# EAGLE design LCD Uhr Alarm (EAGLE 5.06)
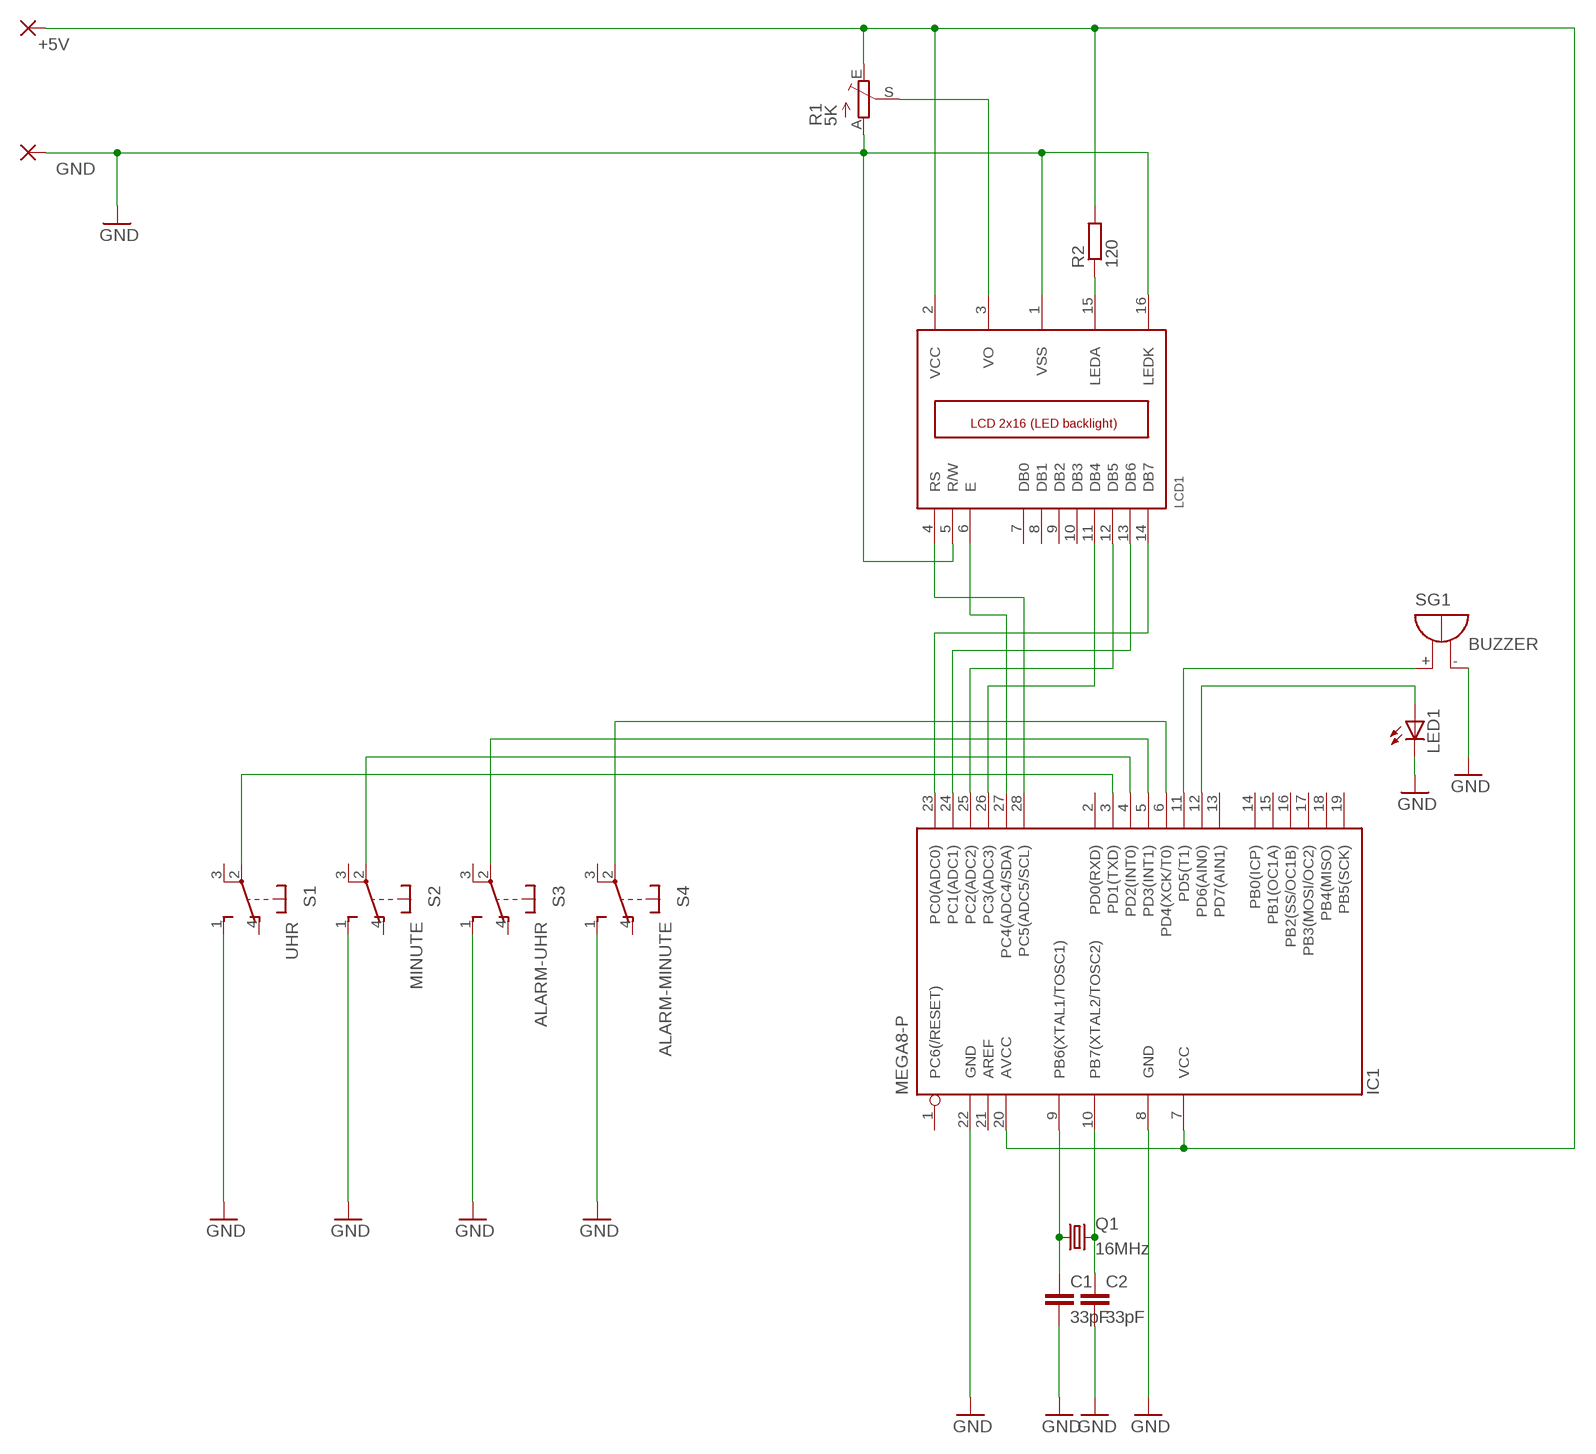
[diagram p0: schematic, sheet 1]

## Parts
+5V  WIREPAD2,54/1,0  [2,54/1,0]
C1  33pF  C2,5-3  [C2.5-3]
C2  33pF  C2,5-3  [C2.5-3]
GND  WIREPAD2,54/1,0  [2,54/1,0]
IC1  MEGA8-P  [DIL28-3]
LCD1  LCD_2X16  [HY-1602F]
LED1  LED5MM  [LED5MM]
Q1  16MHz  CRYSTALHC18U-V  [HC18U-V]
R1  5K  TRIM_EU-CA6V  [CA6V]
R2  120  R-EU_0207/10  [0207/10]
S1  UHR  SRK  [SRK]
S2  MINUTE  SRK  [SRK]
S3  ALARM-UHR  SRK  [SRK]
S4  ALARM-MINUTE  SRK  [SRK]
SG1  BUZZER  EB2505  [EB2505]

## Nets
GND: C1.2 C2.2 GND.1(P) IC1.8(GND) IC1.22(GND) LCD1.1(VSS) LCD1.5(R/W) LCD1.16(LEDK) LED1.K(C) R1.A S1.1(S) S2.1(S) S3.1(S) S4.1(S) SG1.-
N$1: IC1.11(PD5(T1)) SG1.+
N$2: +5V.1(P) IC1.7(VCC) IC1.20(AVCC) LCD1.2(VCC) R1.E R2.2
N$3: LCD1.3(VO) R1.S
N$4: IC1.3(PD1(TXD)) S1.2(P)
N$5: IC1.26(PC3(ADC3)) LCD1.11(DB4)
N$6: IC1.25(PC2(ADC2)) LCD1.12(DB5)
N$7: IC1.24(PC1(ADC1)) LCD1.13(DB6)
N$8: IC1.12(PD6(AIN0)) LED1.A
N$9: IC1.23(PC0(ADC0)) LCD1.14(DB7)
N$10: LCD1.15(LEDA) R2.1
N$11: IC1.28(PC5(ADC5/SCL)) LCD1.4(RS)
N$12: IC1.4(PD2(INT0)) S2.2(P)
N$13: C2.1 IC1.10(PB7(XTAL2/TOSC2)) Q1.2
N$14: C1.1 IC1.9(PB6(XTAL1/TOSC1)) Q1.1
N$15: IC1.5(PD3(INT1)) S3.2(P)
N$16: IC1.27(PC4(ADC4/SDA)) LCD1.6(E)
N$17: IC1.6(PD4(XCK/T0)) S4.2(P)
Unconnected: IC1.1(PC6(/RESET)) IC1.2(PD0(RXD)) IC1.13(PD7(AIN1)) IC1.14(PB0(ICP)) IC1.15(PB1(OC1A)) IC1.16(PB2(SS/OC1B)) IC1.17(PB3(MOSI/OC2)) IC1.18(PB4(MISO)) IC1.19(PB5(SCK)) IC1.21(AREF) LCD1.7(DB0) LCD1.8(DB1) LCD1.9(DB2) LCD1.10(DB3) S1.3(P) S1.4(O) S2.3(P) S2.4(O) S3.3(P) S3.4(O) S4.3(P) S4.4(O)

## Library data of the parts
+5V GND = wirepad:WIREPAD: Wire PAD connect wire on PCB
C1 C2 = capacitor-wima:C: CAPACITOR
IC1 = atmel:MEGA8-P: MICROCONTROLLER 8 Kbytes FLASH, 1 kbytes SRAM, 512 bytes EEPROM, USART, 4-channel 10 bit ADC, 2-channel 8 bit ADC Pin compatible with Atmega48, ATMega88, ATMega168 Source: avr.lbr
LCD1 = lcd_2x16_led_backlight:LCD_2X16
LED1 = led:LED: LED
Q1 = crystal:CRYSTAL: CRYSTAL
R1 = pot:TRIM_EU-: POTENTIOMETER
R2 = resistor:R-EU_: RESISTOR, European symbol
S1-S4 = switch-misc:SRK: SWITCH
SG1 = buzzer:EB2505: BUZZER

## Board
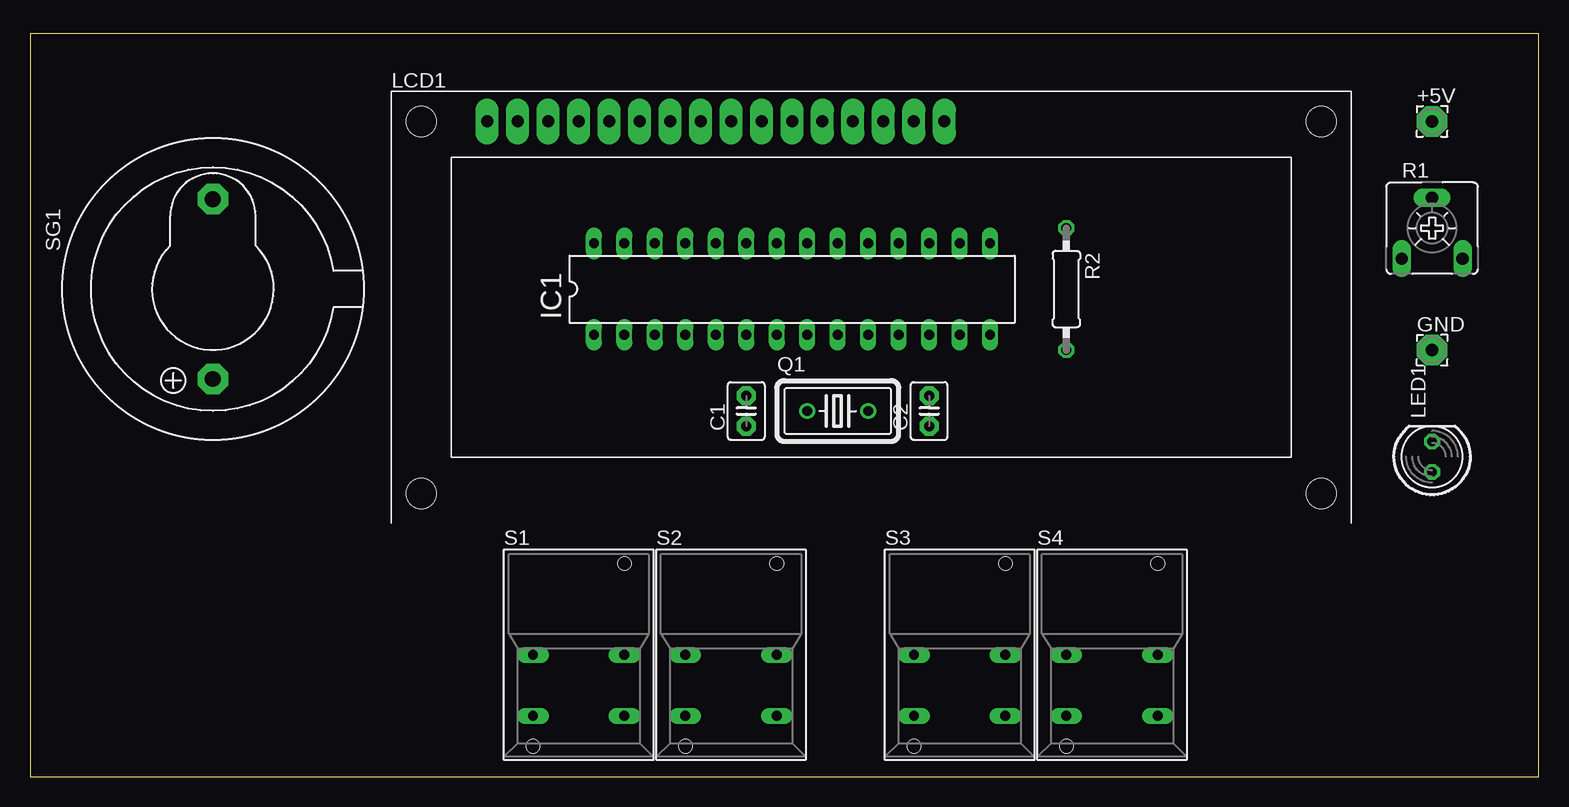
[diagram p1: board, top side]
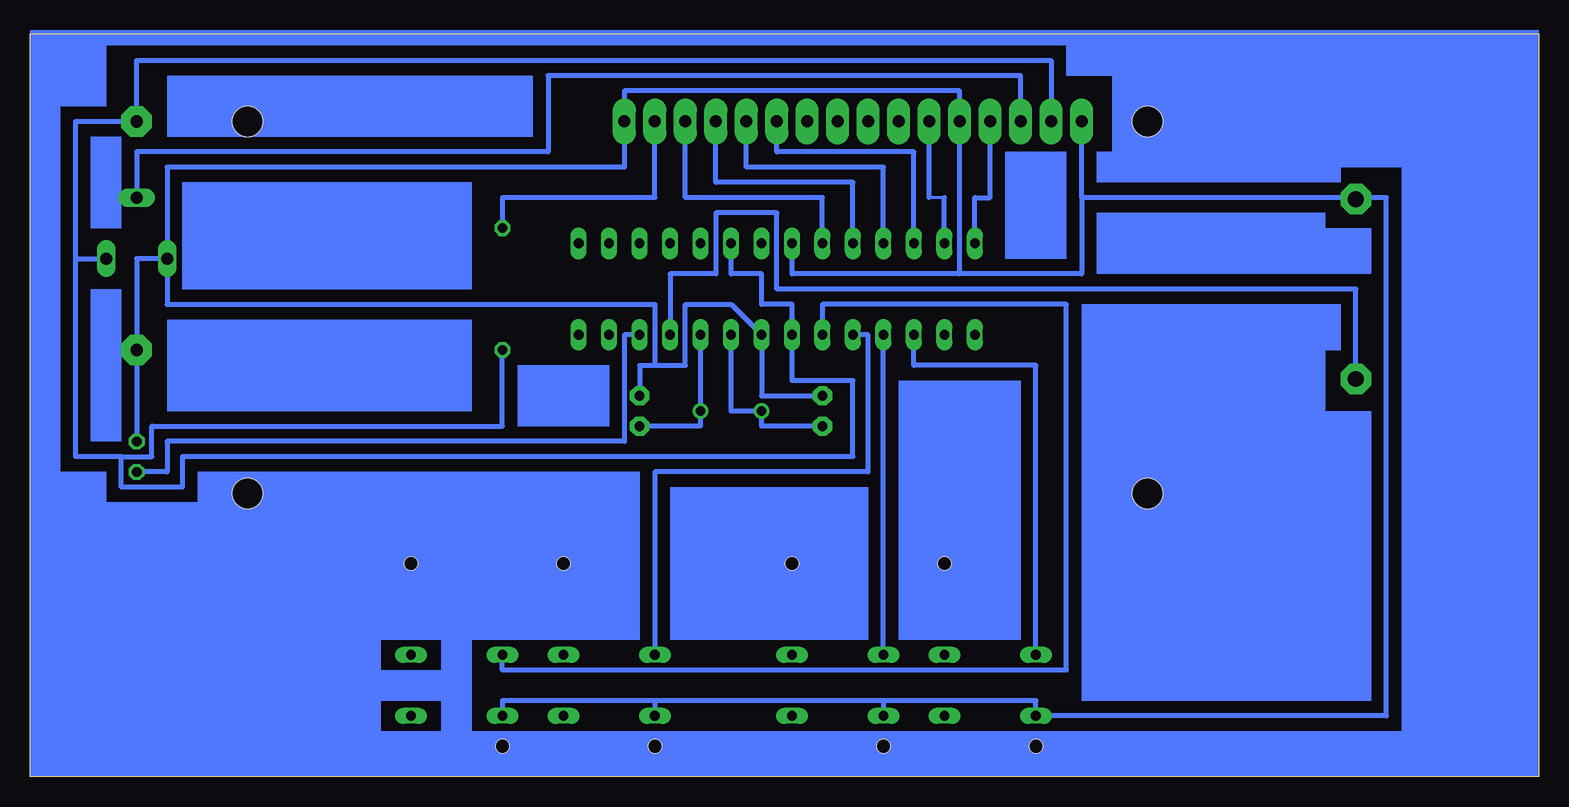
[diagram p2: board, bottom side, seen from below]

Size 125.71 x 61.9 mm. Coordinates in mm from the lower left corner, seen from the top.
Outline: 0,0 125.71,0 125.71,61.9 0,61.9 0,0
Copper layers (1*16): Top 0.035mm / dielectric 1.5mm / Bottom 0.035mm
Design rules "default": minimum track width 10mil, minimum drill 24mil, track to track 8mil, track to pad 8mil, pad to pad 8mil, via to via 8mil, smd to smd 8mil, copper to edge 40mil, drill to drill 8mil, minimum pad ring 10mil, minimum via ring 8mil, stop-mask expansion 4mil, vias tented up to drill 0mil, thermal gap 10mil

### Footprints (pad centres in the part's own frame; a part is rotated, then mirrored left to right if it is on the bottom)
2,54/1,0 = drill 1.016 pad 2.54 octagon: 1 0,0
C2.5-3 = drill 0.813 pad 1.6 octagon: 1 -1.27,0; 2 1.27,0
DIL28-3 = drill 0.813 long: 1 -16.51,-3.81; 2 -13.97,-3.81; 3 -11.43,-3.81; 4 -8.89,-3.81; 5 -6.35,-3.81; 6 -3.81,-3.81; 7 -1.27,-3.81; 8 1.27,-3.81; 9 3.81,-3.81; 10 6.35,-3.81; 11 8.89,-3.81; 12 11.43,-3.81; 13 13.97,-3.81; 14 16.51,-3.81; 15 16.51,3.81; 16 13.97,3.81; 17 11.43,3.81; 18 8.89,3.81; 19 6.35,3.81; 20 3.81,3.81; 21 1.27,3.81; 22 -1.27,3.81; 23 -3.81,3.81; 24 -6.35,3.81; 25 -8.89,3.81; 26 -11.43,3.81; 27 -13.97,3.81; 28 -16.51,3.81
HY-1602F = drill 1 pad 1.93 long: 1 2.54,0; 2 5.08,0; 3 7.62,0; 4 10.16,0; 5 12.7,0; 6 15.24,0; 7 17.78,0; 8 20.32,0; 9 22.86,0; 10 25.4,0; 11 27.94,0; 12 30.48,0; 13 33.02,0; 14 35.56,0; 15 38.1,0; 16 40.64,0 | hole 2.5: -2.96,0; 72.04,0; -2.96,-31; 72.04,-31
LED5MM = drill 0.813 octagon: A -1.27,0; K 1.27,0
HC18U-V = drill 0.813 round: 1 -2.54,0; 2 2.54,0
CA6V = drill 1.016 long: A -2.54,-2.54; E 2.54,-2.54; S 0,2.54
0207/10 = drill 0.813 octagon: 1 -5.08,0; 2 5.08,0
SRK = drill 0.813 long: 1 -3.81,-5.08; 2 -3.81,0; 3 3.81,0; 4 3.81,-5.08 | hole 1.118: -3.81,-7.62; 3.81,7.62
EB2505 = drill 1.321 pad 2.54 octagon: + -7.493,0; - 7.493,0

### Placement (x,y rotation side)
+5V  116.84,54.61 0 top
C1  59.69,30.48 90 top
C2  74.93,30.48 90 top
GND  116.84,35.56 0 top
IC1  63.5,40.64 0 top
LCD1  35.56,54.61 0 top
LED1  116.84,26.67 90 top
Q1  67.31,30.48 0 top
R1  116.84,45.72 0 top
R2  86.36,40.64 270 top
S1  45.72,10.16 0 top
S2  58.42,10.16 0 top
S3  77.47,10.16 0 top
S4  90.17,10.16 0 top
SG1  15.24,40.64 90 top

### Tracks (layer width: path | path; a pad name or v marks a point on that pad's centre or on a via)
GND
  Bottom 0.254: 15.24,48.26 SG1.- | 73.66,34.29 74.93,34.29
  Bottom 0.406: LED1.K GND.1 116.84,43.18 R1.A | IC1.22 62.23,41.91 48.26,41.91 | 38.1,48.26 38.1,41.91 48.26,41.91 | 38.1,48.26 LCD1.1 | 38.1,48.26 15.24,48.26 12.7,48.26 12.7,5.08 S1.1 41.91,6.35 54.61,6.35 | R1.A 114.3,50.8 76.2,50.8 LCD1.16 76.2,57.15 48.26,57.15 LCD1.5 48.26,41.91 | 54.61,6.35 S2.1 | 73.66,6.35 S3.1 | 54.61,6.35 73.66,6.35 | S4.1 86.36,6.35 73.66,6.35 | C1.2 64.77,31.75 IC1.8 67.31,39.37 71.12,39.37 71.12,34.29 74.93,34.29 C2.2 | R1.A 114.3,39.37 73.66,39.37 73.66,34.29
N$1
  Bottom 0.406: IC1.11 72.39,41.91 68.58,41.91 68.58,46.99 63.5,46.99 63.5,40.64 15.24,40.64 SG1.+
N$2
  Bottom 0.406: R2.2 86.36,29.21 115.57,29.21 115.57,26.67 118.11,26.67 | 118.11,26.67 118.11,24.13 113.03,24.13 113.03,26.67 57.15,26.67 57.15,33.02 62.23,33.02 IC1.7 62.23,39.37 64.77,39.37 64.77,41.91 67.31,41.91 IC1.20 | LCD1.2 40.64,59.69 116.84,59.69 +5V.1 121.92,54.61 121.92,43.18 | 118.11,26.67 121.92,26.67 121.92,43.18 | 121.92,43.18 R1.E
N$3
  Bottom 0.406: R1.S 116.84,52.07 82.55,52.07 82.55,58.42 43.18,58.42 LCD1.3
N$4
  Bottom 0.406: S1.2 41.91,34.29 52.07,34.29 IC1.3
N$5
  Bottom 0.406: IC1.26 52.07,52.07 63.5,52.07 LCD1.11
N$6
  Bottom 0.406: IC1.25 54.61,50.8 66.04,50.8 LCD1.12
N$7
  Bottom 0.406: IC1.24 57.15,49.53 68.58,49.53 LCD1.13
N$8
  Bottom 0.406: LED1.A 114.3,25.4 114.3,27.94 76.2,27.94 76.2,36.83 IC1.12
N$9
  Bottom 0.406: IC1.23 59.69,48.26 71.12,48.26 LCD1.14
N$10
  Bottom 0.406: R2.1 86.36,48.26 73.66,48.26 LCD1.15
N$11
  Bottom 0.406: IC1.28 46.99,48.26 45.72,48.26 LCD1.4
N$12
  Bottom 0.406: S2.2 IC1.4
N$13
  Bottom 0.406: C2.1 69.85,29.21 Q1.2 IC1.10
N$14
  Bottom 0.406: C1.1 64.77,29.21 Q1.1 67.31,30.48 IC1.9
N$15
  Bottom 0.406: S3.2 73.66,25.4 55.88,25.4 55.88,36.83 IC1.5
N$16
  Bottom 0.254: 49.53,48.26 50.8,48.26
  Bottom 0.406: IC1.27 49.53,48.26 | 50.8,48.26 LCD1.6
N$17
  Bottom 0.406: IC1.6 59.69,39.37 39.37,39.37 39.37,8.89 86.36,8.89 S4.2
(copper drawn outside any net)
  shapes: Bottom area x30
